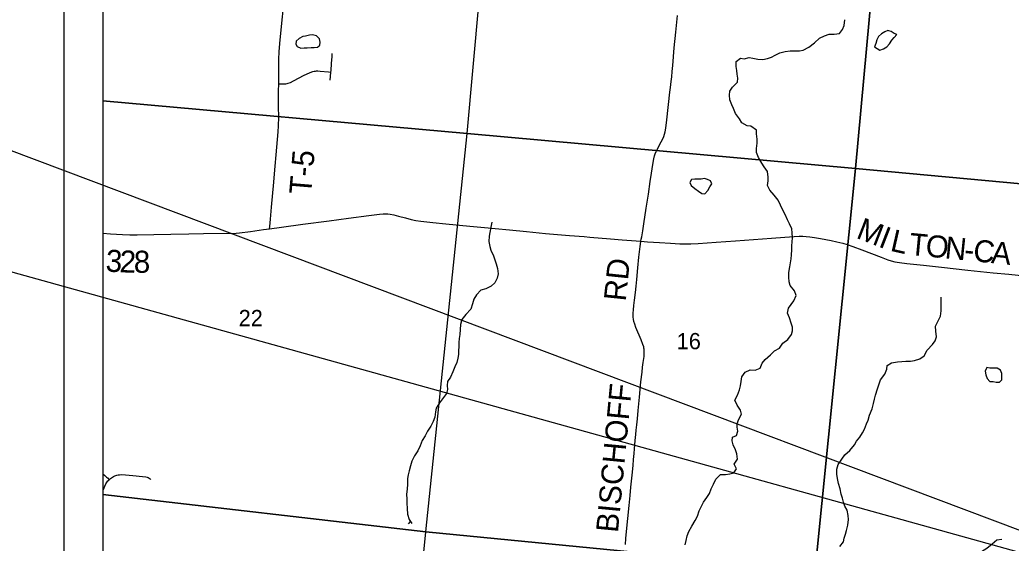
# Model space of a CAD drawing. Extents: x 831 to 1552, y 430 to 870.
# Drawn here: x 1246.5 to 1297.6, y 727.9 to 754.9 of the extents above; entities that cross this region are included whole.
import ezdxf

# ---------------------------------------------------------------- set-up
doc = ezdxf.new("R2010")
doc.units = 0
for name, color, linetype in [('GM_X_Corporation', 7, 'Continuous'), ('GM_X_County_Road', 7, 'Continuous'), ('GM_X_County_Road_Text', 7, 'Continuous'), ('GM_X_Minor_Lake', 7, 'Continuous'), ('GM_X_Minor_River', 7, 'Continuous'), ('GM_X_Section_Text', 7, 'Continuous'), ('GM_X_Township_Road', 7, 'Continuous'), ('GM_X_Township_Road_Text', 7, 'Continuous'), ('SH_Data', 7, 'Continuous'), ('SH_Text', 7, 'Continuous')]:
    doc.layers.add(name, color=color, linetype=linetype)

msp = doc.modelspace()

# ---------------------------------------------------------------- linework, layer by layer
at = {"layer": 'GM_X_Corporation'}
for points in [[(1250.766, 764.525), (1250.766, 750.702), (1269.535, 749.022), (1271.38, 769.351), (1251.406, 771.138)], [(1271.38, 769.351), (1291.379, 767.224), (1289.554, 747.22), (1269.535, 749.022)], [(1291.379, 767.224), (1311.293, 765.037), (1309.391, 745.383), (1289.554, 747.22)], [(1250.766, 750.702), (1250.766, 730.422), (1267.407, 728.501), (1269.535, 749.022)], [(1269.535, 749.022), (1289.554, 747.22), (1287.469, 726.554), (1267.407, 728.501)], [(1289.554, 747.22), (1309.391, 745.383), (1307.365, 724.655), (1287.469, 726.554)], [(1250.766, 730.422), (1250.766, 710.102), (1265.456, 708.606), (1267.407, 728.501)], [(1267.407, 728.501), (1287.469, 726.554), (1285.616, 706.68), (1265.456, 708.606)]]:
    msp.add_lwpolyline(points, close=True, dxfattribs=at)
msp.add_lwpolyline([(1307.479, 765.521), (1280.784, 768.299), (1273.97, 769.031), (1271.262, 769.221), (1261.379, 770.165), (1258.675, 770.41), (1250.766, 771.115), (1250.766, 667.013)], dxfattribs=at)
at = {"layer": 'GM_X_County_Road'}
for points in [[(1259.362, 744.12), (1259.974, 744.206), (1261.082, 744.357), (1262.439, 744.528), (1263.424, 744.665), (1264.47, 744.803), (1265.024, 744.872), (1265.209, 744.885), (1265.332, 744.886), (1265.454, 744.878), (1265.576, 744.862), (1265.758, 744.827), (1265.998, 744.769), (1266.358, 744.673), (1266.66, 744.598), (1266.905, 744.55), (1267.151, 744.511), (1267.769, 744.441), (1268.449, 744.371), (1269.685, 744.25), (1270.427, 744.179), (1270.983, 744.126), (1271.726, 744.06), (1272.592, 743.974), (1273.582, 743.88), (1274.82, 743.772), (1275.562, 743.71), (1275.87, 743.686), (1276.922, 743.598), (1277.531, 743.549), (1278.49, 743.47)], [(1250.766, 743.884), (1251.171, 743.855), (1251.792, 743.821), (1252.165, 743.81), (1252.538, 743.81), (1253.408, 743.826), (1254.278, 743.844), (1255.21, 743.857), (1255.956, 743.867), (1257.634, 743.891), (1257.819, 743.906), (1258.375, 743.978), (1259.052, 744.076), (1259.362, 744.12)], [(1278.49, 743.47), (1278.831, 743.442), (1279.452, 743.408), (1280.009, 743.375), (1280.506, 743.347), (1280.817, 743.34), (1281.065, 743.345), (1281.438, 743.364), (1282.366, 743.433), (1283.358, 743.501), (1285.218, 743.628), (1285.899, 743.684), (1286.394, 743.721), (1286.642, 743.731), (1286.827, 743.73), (1287.012, 743.722), (1287.195, 743.706), (1287.439, 743.673), (1287.742, 743.618), (1288.287, 743.506), (1288.59, 743.443), (1288.891, 743.374), (1289.127, 743.311), (1289.417, 743.211), (1289.88, 743.031), (1290.865, 742.648), (1291.215, 742.517), (1291.393, 742.46), (1291.576, 742.417), (1291.822, 742.377), (1292.193, 742.331), (1293.058, 742.24), (1293.984, 742.135), (1295.343, 741.987), (1296.641, 741.854), (1297.445, 741.77), (1298.557, 741.652)]]:
    msp.add_lwpolyline(points, dxfattribs=at)
at = {"layer": 'GM_X_Minor_Lake'}
for points in [[(1291.263, 754.314), (1291.21, 754.328), (1291.058, 754.269), (1290.882, 754.165), (1290.735, 754.015), (1290.642, 753.841), (1290.587, 753.667), (1290.531, 753.485), (1290.81, 753.314)], [(1290.81, 753.314), (1290.993, 753.381), (1291.162, 753.485), (1291.293, 753.651), (1291.424, 753.824), (1291.548, 753.975), (1291.679, 754.125), (1291.543, 754.18), (1291.384, 754.281), (1291.263, 754.314)], [(1261.917, 753.547), (1261.952, 753.579), (1261.977, 753.73), (1261.941, 753.906), (1261.776, 754.06), (1261.571, 754.1), (1261.412, 754.087), (1261.221, 754.044), (1261.069, 754.015), (1260.885, 753.911), (1260.732, 753.775), (1260.722, 753.623)], [(1260.722, 753.623), (1260.789, 753.501), (1260.97, 753.423), (1261.153, 753.444), (1261.304, 753.434), (1261.502, 753.455), (1261.669, 753.453), (1261.829, 753.466), (1261.917, 753.547)], [(1282.117, 746.387), (1282.145, 746.437), (1282.078, 746.582), (1281.927, 746.652), (1281.761, 746.7), (1281.593, 746.679), (1281.426, 746.673), (1281.267, 746.675), (1281.092, 746.662), (1281.021, 746.503)], [(1281.021, 746.503), (1281.088, 746.343), (1281.268, 746.189), (1281.456, 746.05), (1281.637, 745.941), (1281.789, 745.909), (1281.935, 746.09), (1282.052, 746.271), (1282.117, 746.387)], [(1296.315, 736.967), (1296.229, 736.778), (1296.257, 736.588), (1296.339, 736.412), (1296.474, 736.251), (1296.641, 736.249), (1296.8, 736.217), (1296.967, 736.215), (1297.021, 736.267)], [(1297.021, 736.267), (1297.09, 736.335), (1297.092, 736.495), (1297.087, 736.669), (1297.013, 736.838), (1296.839, 736.938), (1296.664, 736.933), (1296.475, 736.935), (1296.315, 736.967)]]:
    msp.add_lwpolyline(points, dxfattribs=at)
at = {"layer": 'GM_X_Minor_River'}
for points in [[(1285.051, 746.783), (1285.009, 747.065), (1284.845, 747.31), (1284.719, 747.501), (1284.555, 747.785), (1284.452, 748.052), (1284.455, 748.25), (1284.481, 748.523), (1284.476, 748.736), (1284.449, 749.01), (1284.452, 749.2), (1284.158, 749.394), (1283.968, 749.411), (1283.697, 749.582), (1283.578, 749.773), (1283.369, 750.057), (1283.258, 750.317), (1283.169, 750.508), (1283.081, 750.752), (1283.054, 750.996), (1283.079, 751.201), (1283.219, 751.404), (1283.465, 751.668), (1283.483, 751.873), (1283.455, 752.086), (1283.428, 752.276), (1283.392, 752.482), (1283.403, 752.733), (1283.618, 752.898), (1283.815, 752.873), (1284.067, 752.938), (1284.256, 752.905), (1284.521, 752.849), (1284.772, 752.838), (1285.023, 752.889), (1285.214, 752.955), (1285.405, 753.067), (1285.657, 753.178), (1285.917, 753.251), (1286.175, 753.286), (1286.449, 753.275), (1286.669, 753.28), (1286.86, 753.323), (1287.142, 753.464), (1287.434, 753.697), (1287.688, 753.937), (1287.948, 754.048), (1288.199, 754.136), (1288.45, 754.133), (1288.732, 754.183), (1288.879, 754.387), (1288.957, 754.583), (1288.992, 754.887)], [(1280.77, 727.827), (1280.819, 728.062), (1280.875, 728.297), (1280.969, 728.516), (1281.117, 728.803), (1281.295, 729.09), (1281.404, 729.309), (1281.499, 729.589), (1281.593, 729.785), (1281.71, 730.034), (1281.895, 730.275), (1282.019, 730.471), (1282.121, 730.713), (1282.23, 730.955), (1282.355, 731.212), (1282.593, 731.452), (1282.852, 731.464), (1283.08, 731.492), (1283.278, 731.543), (1283.418, 731.754), (1283.292, 731.999), (1283.462, 732.24), (1283.443, 732.521), (1283.369, 732.727), (1283.243, 732.994), (1283.193, 733.185), (1283.21, 733.375), (1283.417, 733.471), (1283.488, 733.698), (1283.452, 733.896), (1283.455, 734.094), (1283.541, 734.305), (1283.673, 734.57), (1283.63, 734.775), (1283.451, 735.028), (1283.333, 735.28), (1283.465, 735.552), (1283.568, 735.817), (1283.623, 736.022), (1283.657, 736.257), (1283.698, 736.492), (1283.868, 736.733), (1284.128, 736.852), (1284.378, 736.841), (1284.638, 736.937), (1284.747, 737.186), (1284.887, 737.39), (1285.163, 737.615), (1285.378, 737.833), (1285.638, 737.974), (1285.809, 738.23), (1286.069, 738.41), (1286.247, 738.666), (1286.295, 738.863), (1286.298, 739.053), (1286.24, 739.251), (1286.144, 739.526), (1286.049, 739.763), (1286.097, 740.02), (1286.237, 740.216), (1286.368, 740.412), (1286.493, 740.685), (1286.397, 740.914), (1286.181, 741.19), (1286.137, 741.38), (1286.118, 741.624), (1286.121, 741.867), (1286.162, 742.156), (1286.203, 742.36), (1286.229, 742.573), (1286.246, 742.778), (1286.272, 743.036), (1286.275, 743.241), (1286.285, 743.439), (1286.303, 743.644), (1286.291, 743.91), (1286.271, 744.115), (1286.153, 744.368), (1286.041, 744.574), (1285.931, 744.849), (1285.782, 745.117), (1285.686, 745.331), (1285.568, 745.591), (1285.351, 745.852), (1285.134, 746.098), (1285.023, 746.342), (1285.041, 746.593), (1285.051, 746.783)], [(1270.807, 744.464), (1270.758, 744.198), (1270.709, 743.918), (1270.676, 743.728), (1270.665, 743.469), (1270.708, 743.211), (1270.766, 743.012), (1270.892, 742.729), (1270.965, 742.516), (1271.038, 742.317), (1271.111, 742.073), (1271.138, 741.792), (1271.09, 741.579), (1270.965, 741.338), (1270.773, 741.165), (1270.505, 741.031), (1270.246, 740.951), (1270.023, 740.71), (1269.883, 740.491), (1269.819, 740.256), (1269.725, 739.976), (1269.478, 739.706), (1269.262, 739.442), (1269.198, 739.177), (1269.187, 738.926), (1269.161, 738.676), (1269.136, 738.471), (1269.118, 738.251), (1269.108, 738.053), (1269.097, 737.833), (1269.095, 737.643), (1269.062, 737.446), (1269.006, 737.226), (1268.904, 736.999), (1268.802, 736.75), (1268.677, 736.477), (1268.523, 736.244), (1268.512, 736.039), (1268.525, 735.841), (1268.477, 735.629), (1268.315, 735.433), (1268.114, 735.154), (1267.951, 734.883), (1267.918, 734.685), (1267.869, 734.42), (1267.783, 734.193), (1267.666, 733.944), (1267.503, 733.695), (1267.371, 733.446), (1267.216, 733.204), (1267.121, 732.932), (1266.996, 732.683), (1266.826, 732.427), (1266.686, 732.147), (1266.622, 731.905), (1266.558, 731.655), (1266.495, 731.443), (1266.47, 731.253), (1266.474, 730.964), (1266.448, 730.706), (1266.422, 730.448), (1266.433, 730.182), (1266.431, 729.977), (1266.45, 729.711), (1266.477, 729.422), (1266.55, 729.148), (1266.699, 728.941)], [(1290.837, 736.332), (1291.054, 736.619), (1291.156, 736.883), (1291.181, 737.081), (1291.41, 737.207), (1291.707, 737.257), (1291.928, 737.285), (1292.133, 737.29), (1292.384, 737.302), (1292.59, 737.338), (1292.864, 737.418), (1293.079, 737.568), (1293.235, 737.87), (1293.512, 738.148), (1293.659, 738.351), (1293.714, 738.548), (1293.68, 738.837), (1293.676, 739.103), (1293.801, 739.375), (1293.933, 739.609), (1293.959, 739.89), (1293.962, 740.134), (1293.958, 740.4), (1293.953, 740.597)], [(1288.747, 727.742), (1288.932, 727.99), (1288.965, 728.18), (1289.028, 728.384), (1289.091, 728.581), (1289.156, 728.853), (1289.182, 729.134), (1289.177, 729.347), (1289.12, 729.629), (1289.001, 729.828), (1288.927, 730.041), (1288.884, 730.239), (1288.811, 730.438), (1288.753, 730.712), (1288.673, 730.994), (1288.616, 731.245), (1288.581, 731.481), (1288.584, 731.732), (1288.663, 731.981), (1288.841, 732.253), (1289.003, 732.471), (1289.264, 732.696), (1289.488, 732.982), (1289.605, 733.178), (1289.767, 733.382), (1289.914, 733.6), (1290.008, 733.797), (1290.11, 734.061), (1290.203, 734.258), (1290.275, 734.508), (1290.408, 734.833), (1290.48, 735.121), (1290.521, 735.333), (1290.584, 735.553), (1290.687, 735.863), (1290.774, 736.136), (1290.837, 736.332)], [(1266.617, 729.054), (1266.501, 728.921)], [(1293.398, 726.677), (1293.741, 726.787), (1293.985, 726.837), (1294.176, 726.888), (1294.488, 726.937), (1294.747, 727.003), (1295.021, 727.076), (1295.288, 727.156), (1295.525, 727.237), (1295.769, 727.348), (1296.045, 727.489), (1296.32, 727.66), (1296.581, 727.893), (1296.835, 728.087), (1297.078, 728.13)]]:
    msp.add_lwpolyline(points, dxfattribs=at)
at = {"layer": 'GM_X_Township_Road'}
for points in [[(1259.835, 751.576), (1259.839, 751.826), (1259.838, 751.923), (1259.847, 752.358), (1259.849, 752.855), (1259.862, 753.229), (1259.897, 753.663), (1259.979, 754.53), (1260.093, 755.706), (1260.146, 756.263), (1260.235, 757.254), (1260.298, 757.934), (1260.358, 758.616), (1260.454, 759.731), (1260.486, 760.088)], [(1278.49, 743.47), (1278.515, 743.577), (1278.536, 743.699), (1278.585, 744.006), (1278.641, 744.374), (1278.76, 745.185), (1278.88, 745.907), (1278.973, 746.544), (1279.046, 746.987), (1279.113, 747.423), (1279.159, 747.713), (1279.193, 747.866), (1279.233, 747.98), (1279.285, 748.096), (1279.338, 748.207), (1279.543, 748.59), (1279.626, 748.758), (1279.673, 748.874), (1279.711, 748.994), (1279.74, 749.116), (1279.771, 749.301), (1279.823, 749.733), (1279.988, 751.152), (1280.018, 751.4), (1280.035, 751.55), (1280.054, 751.703), (1280.079, 751.937), (1280.105, 752.22), (1280.135, 752.526), (1280.215, 753.445), (1280.292, 754.245), (1280.378, 755.111)], [(1262.518, 752.183), (1262.529, 752.278), (1262.552, 752.631), (1262.583, 752.998), (1262.593, 753.151)], [(1259.835, 751.576), (1259.969, 751.581), (1260.202, 751.59), (1260.263, 751.6), (1260.322, 751.615), (1260.438, 751.658), (1260.604, 751.739), (1261.145, 752.023), (1261.425, 752.156), (1261.54, 752.201), (1261.599, 752.219), (1261.66, 752.233), (1261.721, 752.242), (1261.783, 752.247), (1261.844, 752.248), (1261.968, 752.24), (1262.399, 752.195), (1262.518, 752.183)], [(1262.479, 751.773), (1262.495, 751.968), (1262.518, 752.183)], [(1259.362, 744.12), (1259.375, 744.236), (1259.414, 744.605), (1259.469, 745.223), (1259.581, 746.521), (1259.618, 746.954), (1259.74, 748.313), (1259.809, 749.117), (1259.826, 749.426), (1259.834, 749.859), (1259.831, 750.417), (1259.828, 750.975), (1259.828, 751.207), (1259.835, 751.576)], [(1277.693, 727.846), (1277.716, 728.153), (1277.75, 728.524), (1277.887, 729.857), (1277.94, 730.374), (1277.977, 730.8), (1278.012, 731.115), (1278.041, 731.424), (1278.086, 731.918), (1278.117, 732.227), (1278.144, 732.534), (1278.166, 732.781), (1278.203, 733.205), (1278.233, 733.524), (1278.254, 733.743), (1278.283, 734.014), (1278.315, 734.324), (1278.36, 734.756), (1278.424, 735.436), (1278.497, 736.24), (1278.551, 736.733), (1278.583, 736.979), (1278.614, 737.225), (1278.653, 737.534), (1278.665, 737.721), (1278.665, 737.847), (1278.66, 737.91), (1278.651, 737.973), (1278.637, 738.034), (1278.599, 738.154), (1278.509, 738.388), (1278.238, 739.036), (1278.175, 739.211), (1278.137, 739.333), (1278.11, 739.453), (1278.1, 739.563), (1278.1, 739.763), (1278.117, 739.936), (1278.137, 740.156), (1278.167, 740.439), (1278.214, 740.839), (1278.247, 741.165), (1278.28, 741.511), (1278.337, 742.1), (1278.391, 742.657), (1278.451, 743.211), (1278.486, 743.455), (1278.49, 743.47)], [(1250.766, 731.505), (1250.781, 731.495), (1250.876, 731.415), (1250.965, 731.328), (1251.007, 731.283), (1251.092, 731.19)], [(1251.092, 731.19), (1251.121, 731.218), (1251.169, 731.258), (1251.22, 731.294), (1251.272, 731.328), (1251.328, 731.357), (1251.385, 731.384), (1251.443, 731.406), (1251.503, 731.424), (1251.564, 731.438), (1251.626, 731.447), (1251.751, 731.454), (1251.939, 731.447), (1252.313, 731.415), (1252.811, 731.357), (1252.996, 731.33), (1253.057, 731.319), (1253.116, 731.298), (1253.166, 731.272), (1253.206, 731.242), (1253.242, 731.209)], [(1250.815, 730.68), (1250.879, 730.857), (1250.932, 730.97), (1250.997, 731.077), (1251.034, 731.127), (1251.076, 731.174), (1251.092, 731.19)]]:
    msp.add_lwpolyline(points, dxfattribs=at)
at = {"layer": 'SH_Data'}
for p, q in [((1248.766, 788.938), (1248.766, 648.938)), ((1250.766, 786.938), (1250.766, 650.938))]:
    msp.add_line(p, q, dxfattribs=at)
at = {"layer": 'SH_Text'}
msp.add_lwpolyline([(1309.717, 724.179), (1213.915, 750.822), (1213.915, 760.257)], close=True, dxfattribs=at)

# ---------------------------------------------------------------- texts
at = {"layer": 'GM_X_County_Road_Text'}
for s, rotation, p in [('M', 338.7844, (1289.532, 743.659)), ('I', 338.8134, (1290.682, 743.212)), ('L', 347.2221, (1291.292, 742.991)), ('T', 354.6336, (1292.279, 742.777)), ('O', 354.1944, (1293.123, 742.698)), ('N', 354.1944, (1294.118, 742.597)), ('C', 354.1943, (1295.577, 742.449)), ('A', 354.1944, (1296.506, 742.354)), ('3', 356.8308, (1250.9, 741.916)), ('2', 357.7752, (1251.619, 741.876)), ('8', 0.1887, (1252.371, 741.848)), ('-', 354.1951, (1295.113, 742.496))]:
    msp.add_text(s, height=1.136, rotation=rotation, dxfattribs=at).set_placement(p)
at = {"layer": 'GM_X_Section_Text'}
for s, p in [('22', (1257.771, 739.099)), ('16', (1280.337, 737.91))]:
    msp.add_text(s, height=0.8371, rotation=0, dxfattribs=at).set_placement(p)
at = {"layer": 'GM_X_Township_Road_Text'}
for s, rotation, p in [('T-5', 85.226, (1261.503, 745.85)), ('RD', 84.0934, (1277.71, 740.354)), ('BISCHOFF', 84.5721, (1277.309, 728.434))]:
    msp.add_text(s, height=1.1364, rotation=rotation, dxfattribs=at).set_placement(p)

doc.saveas('drawing.dxf')
